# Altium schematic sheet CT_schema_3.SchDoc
size 293 x 156 mm
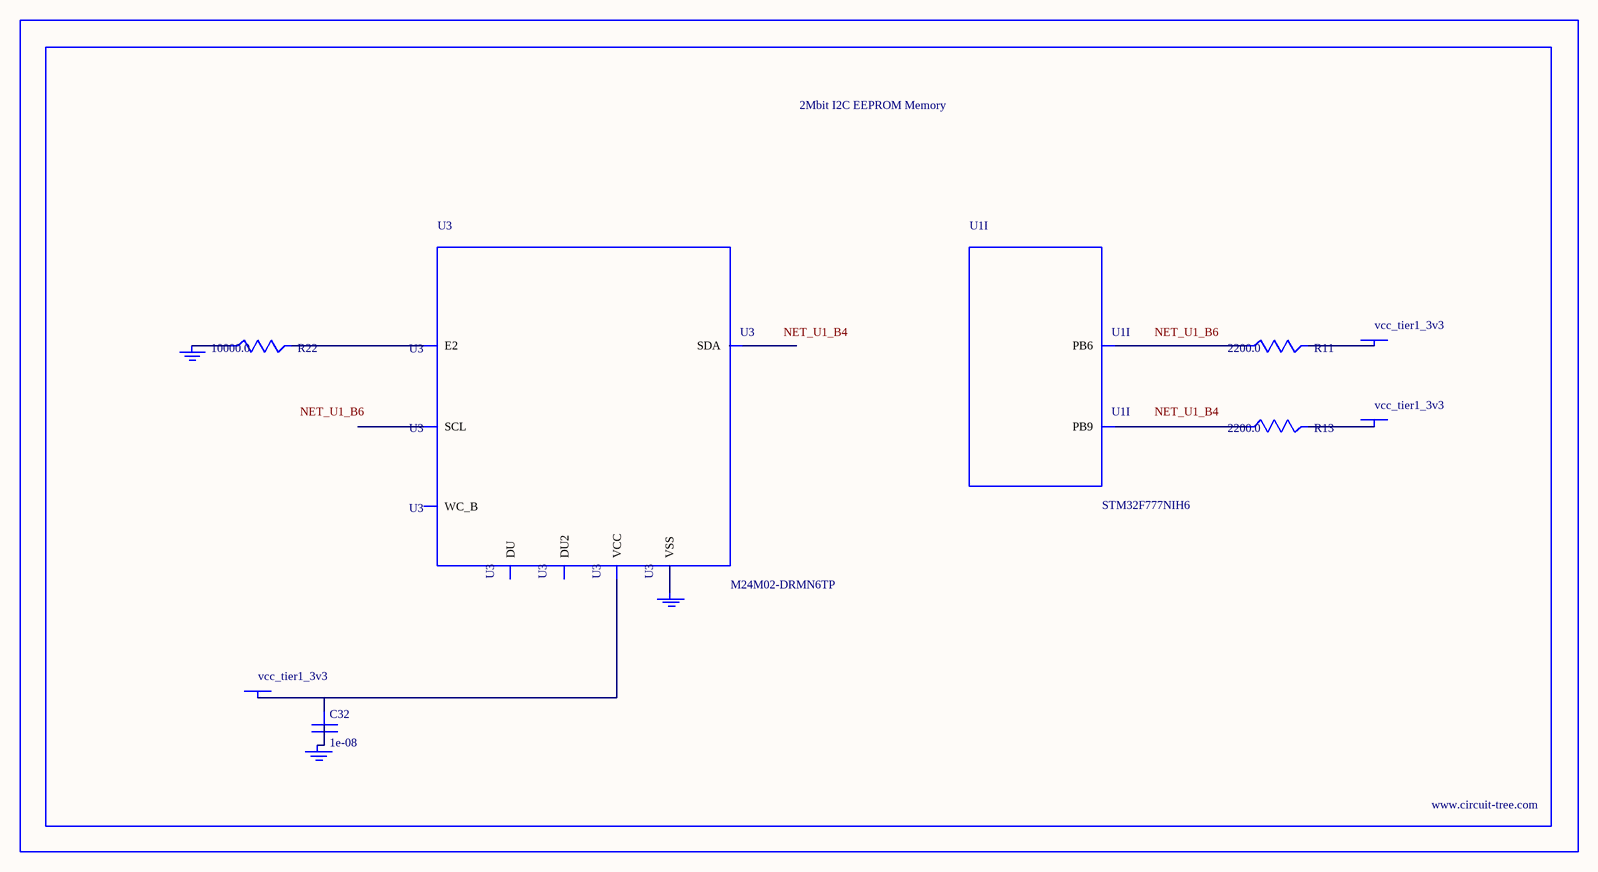
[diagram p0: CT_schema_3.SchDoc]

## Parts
BORDER2  (no value)
C32  1e-08  [C0402]
GND_INSTANCE_2_0  (no value)
GND_INSTANCE_2_1  (no value)
GND_INSTANCE_2_2  (no value)
POWER_INSTANCE_2_0  vcc_tier1_3v3
POWER_INSTANCE_2_1  vcc_tier1_3v3
POWER_INSTANCE_2_2  vcc_tier1_3v3
R11  2200.0  [R0603]
R13  2200.0  [R0603]
R22  10000.0  [R0603]
U1  STM32F777NIH6  [TFBGA216]  (part I of 15)
U3  M24M02-DRMN6TP  [SOIC-8]

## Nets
NetC32_1: C32.1 POWER_INSTANCE_2_0.0(PWR) U3.8(VCC)
NetC32_2: C32.2 GND_INSTANCE_2_1.0(GND)
NetGND_INSTANCE_2_0_0: GND_INSTANCE_2_0.0(GND) R22.1
NetGND_INSTANCE_2_2_0: GND_INSTANCE_2_2.0(GND) U3.4(VSS)
NetPOWER_INSTANCE_2_1_0: POWER_INSTANCE_2_1.0(PWR) R11.2
NetPOWER_INSTANCE_2_2_0: POWER_INSTANCE_2_2.0(PWR) R13.2
NetR11_1: R11.1 U1.B6(PB6)
NetR13_1: R13.1 U1.B4(PB9)
NetR22_2: R22.2 U3.3(E2)

Not connected (* = marked no-connect by the designer): U3 1(DU) 2(DU2) 5(SDA) 6(SCL) 7(WC_B)

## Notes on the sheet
- Labels drawn without touching a wire or pin: NET_U1_B4, NET_U1_B6

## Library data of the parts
BORDER2 = BORDER_PAGE2
C32 = C0402C103K3RAC
GND_INSTANCE_2_0-GND_INSTANCE_2_2 = GND
POWER_INSTANCE_2_0-POWER_INSTANCE_2_2 = PWR
R11 R13 = RC0603JR-072K2L
R22 = RC0603JR-0710KL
